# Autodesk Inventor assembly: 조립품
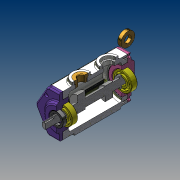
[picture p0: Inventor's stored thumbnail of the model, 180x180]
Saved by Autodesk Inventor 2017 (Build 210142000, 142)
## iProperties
Part Number: 조립품
Material: 일반
Document SubType Name: Assembly
Designer: user
Author: user
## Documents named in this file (9)
- C:\Users\user\Desktop\710606V1044\조립품.iam
- C:\Users\user\Desktop\710606V1044\본체.ipt
- C:\Users\user\Desktop\710606V1044\편심축.ipt
- C:\Users\user\Desktop\710606V1044\앞커버.ipt
- C:\Users\user\Desktop\710606V1044\뒷커버.ipt
- C:\Users\user\Desktop\710606V1044\베어링 6203.ipt
- C:\Users\user\Desktop\710606V1044\베어링 6302.ipt
- C:\Users\user\Desktop\710606V1044\오일실.ipt
- C:\Users\user\Desktop\710606V1044\부시.ipt
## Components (2 placed, 2 different names)
1. 7-베어링 6203:1 — 각도:2
2. 8-오일실:1
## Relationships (1: Angle 1)
- 각도:2 [Angle]: 7-베어링 6203:1
